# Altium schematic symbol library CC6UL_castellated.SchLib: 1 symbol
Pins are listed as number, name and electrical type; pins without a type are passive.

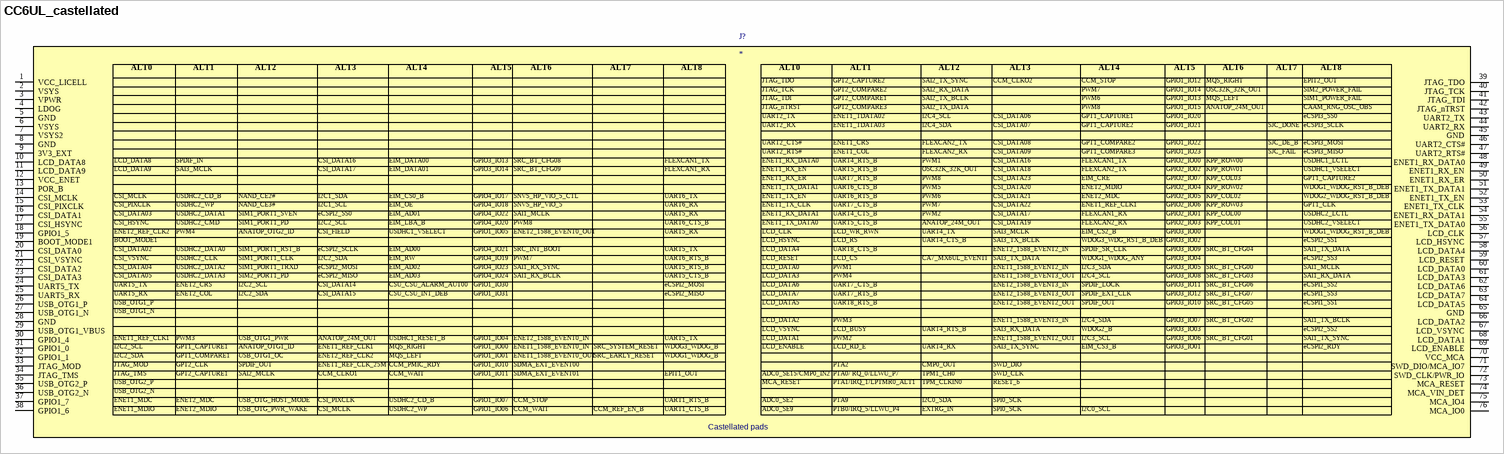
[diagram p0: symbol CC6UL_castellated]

## CC6UL_castellated
designator J?
CC6UL
pins: 1 VCC_LICELL, 2 VSYS, 3 VPWR, 4 LDOG, 5 GND (power), 6 VSYS (power), 7 VSYS2 (power), 8 GND (power), 9 3V3_EXT (power), 10 LCD_DATA8, 11 LCD_DATA9, 12 VCC_ENET (power), 13 POR_B, 14 CSI_MCLK, 15 CSI_PIXCLK, 16 CSI_DATA1, 17 CSI_HSYNC, 18 GPIO1_5 (oc), 19 BOOT_MODE1 (oc), 20 CSI_DATA0 (oc), 21 CSI_VSYNC (oc), 22 CSI_DATA2 (oc), 23 CSI_DATA3 (oc), 24 UART5_TX (oc), 25 UART5_RX (oc), 26 USB_OTG1_P (oc), 27 USB_OTG1_N (oc), 28 GND (power), 29 USB_OTG1_VBUS (oc), 30 GPIO1_4 (oc), 31 GPIO1_0 (oc), 32 GPIO1_1 (oc), 33 JTAG_MOD (oc), 34 JTAG_TMS (oc), 35 USB_OTG2_P (oc), 36 USB_OTG2_N (oc), 37 GPIO1_7 (oc), 38 GPIO1_6 (oc), 39 JTAG_TDO (oc), 40 JTAG_TCK (oc), 41 JTAG_TDI, 42 JTAG_nTRST (oc), 43 UART2_TX (oc), 44 UART2_RX (oc), 45 GND (power), 46 UART2_CTS# (oc), 47 UART2_RTS# (oc), 48 ENET1_RX_DATA0 (oc), 49 ENET1_RX_EN (oc), 50 ENET1_RX_ER (oc), 51 ENET1_TX_DATA1 (oc), 52 ENET1_TX_EN (oc), 53 ENET1_TX_CLK (oc), 54 ENET1_RX_DATA1 (oc), 55 ENET1_TX_DATA0 (oc), 56 LCD_CLK (oc), 57 LCD_HSYNC (oc), 58 LCD_DATA4 (oc), 59 LCD_RESET (oc), 60 LCD_DATA0 (oc), 61 LCD_DATA3 (oc), 62 LCD_DATA6 (oc), 63 LCD_DATA7 (oc), 64 LCD_DATA5 (oc), 65 GND (power), 66 LCD_DATA2, 67 LCD_VSYNC (oc), 68 LCD_DATA1 (oc), 69 LCD_ENABLE (oc), 70 VCC_MCA (power), 71 SWD_DIO/MCA_IO7 (oc), 72 SWD_CLK/PWR_IO (oc), 73 MCA_RESET (oc), 74 MCA_VIN_DET (oc), 75 MCA_IO4 (oc), 76 MCA_IO0 (oc)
